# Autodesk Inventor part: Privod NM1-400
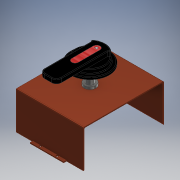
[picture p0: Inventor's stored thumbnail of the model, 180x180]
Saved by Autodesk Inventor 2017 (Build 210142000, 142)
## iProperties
Part Number: Privod NM1-400
Material: Типовые
Document SubType Name: Modeling
Designer: RSagdiev
Density: 1 g/cm^3
Appearance: По умолчанию
Author: RSagdiev
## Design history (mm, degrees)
sketch "Эскиз1"
  geometry: L1 (-37.5, 96.25)-(37.5, 96.25); L2 (37.5, 96.25)-(37.5, 87.75); L3 (37.5, 87.75)-(20.75, 87.75); L4 (-37.5, 87.75)-(-37.5, 96.25); L5 (0, 0)-(119.698, 0); L6 (0, 0)-(-104.809, 0); L7 (0, 94.88)-(0, -60.954); L8 (-20.75, 87.75)-(-16.75, 87.75); L9 (-16.75, 87.75)-(-16.75, 92.75); L10 (-18.75, 94.75)-(-18.75, 94.75); L11 (-20.75, 92.75)-(-20.75, 87.75); L12 (16.75, 87.75)-(16.75, 92.75); L13 (18.75, 94.75)-(18.75, 94.75); L14 (20.75, 87.75)-(16.75, 87.75); L15 (20.75, 92.75)-(20.75, 87.75); L16 (-20.75, 87.75)-(-37.5, 87.75); L17 (-16.75, 87.75)-(-20.75, 87.75); L18 (16.75, 87.75)-(-16.75, 87.75); L19 (20.75, 87.75)-(16.75, 87.75); A1 r 2 centre (-18.75, 92.75) between (-18.75, 94.75) and (-20.75, 92.75); A2 r 2 centre (-18.75, 92.75) between (-16.75, 92.75) and (-18.75, 94.75); A3 r 2 centre (18.75, 92.75) between (18.75, 94.75) and (16.75, 92.75); A4 r 2 centre (18.75, 92.75) between (20.75, 92.75) and (18.75, 94.75); 5 further points
  constraints: 38 end point, 10 point on line, 10 symmetric about line, 8 parallel, 8 point on circle, 4 centre point, 4 horizontal, 4 tangent, 2 perpendicular, 1 concentric, 1 midpoint, 1 vertical, 2 other
  dimensions: "d0" = 87.75 distance between parallel lines of L3 L6 (= 0.5 x Высота); "d1" = 8.5 distance of L1.end L2.end; "d2" = 75 distance between parallel lines of L2 L4 (= 0.5 x Ширина); "d3" = 4 distance of point (-20.75, 94.75) point (-16.75, 94.75); "d4" = 7 distance of point (-16.75, 94.75) L8.end; "d5" = 2 radius of A1 (derived); "d6" = 18.75 distance from line of L4 A1.centre (= 0.25 x d2)
extrude "Выдавливание1" new body sketch "Эскиз1" distance "d7" = 2; taper "d8" = 0 deg
mirror "Зеркальное отражение1"
sketch "Эскиз2"
  geometry: L1 (-37.5, 96.25)-(-37.5, 87.75) reference; L2 (37.5, 87.75)-(37.5, 96.25) reference; L3 (-37.5, -96.25)-(-37.5, -87.75) reference; L4 (37.5, -87.75)-(37.5, -96.25) reference; L5 (-75, 89.75)-(75, 89.75); L6 (75, 89.75)-(75, 87.75); L7 (75, 87.75)-(-75, 87.75); L8 (-75, 87.75)-(-75, 89.75); L9 (-37.5, 87.75)-(-20.75, 87.75) reference
  constraints: 8 end point, 2 parallel, 1 collinear, 1 horizontal, 1 perpendicular
  dimensions: "d13" = 150 distance of L5.start L5.end (= Ширина); "d14" = 2 distance of L5.end L6.end; "d15" = 37.5 distance between parallel lines of L1 L8 (= 0.25 x d13)
extrude "Выдавливание2" join sketch "Эскиз2" distance "d11" = 84 (computed from H1); taper "d12" = 0 deg
mirror "Зеркальное отражение2"
sketch "Эскиз3"
  geometry: L1 (-75, 89.75)-(-37.5, 89.75) reference; L2 (75, -89.75)-(-75, -89.75) reference; L3 (-75, 89.75)-(75, 89.75); L4 (75, 89.75)-(75, -89.75); L5 (75, -89.75)-(-75, -89.75); L6 (-75, -89.75)-(-75, 89.75); 1 further point
  constraints: 8 end point, 2 parallel, 1 horizontal, 1 perpendicular
extrude "Выдавливание3" join sketch "Эскиз3" distance "d16" = 2; taper "d17" = 0 deg
fillet "Сопряжение1" dims "d18" = 2
sketch "Эскиз4"
  geometry: L1 (75, -85.75)-(-75, -85.75) reference; L2 (75, -85.75)-(75, 85.75) reference; L3 (-75, 85.75)-(75, 85.75) reference; L4 (-75, 85.75)-(-75, -85.75) reference; L5 (-75, 85.75)-(-75, -85.75) reference; L6 (-75, -85.75)-(75, 85.75); L7 (75, -85.75)-(75, 85.75) reference; L8 (-75, 85.75)-(75, -85.75); C1 r 5 at (0, 0); 1 further point
  constraints: 4 end point, 1 centre point, 1 coincident
  dimensions: "d19" = 10 diameter of C1
extrude "Выдавливание4" cut sketch "Эскиз4" distance "d20" = 10; taper "d21" = 0 deg
sketch "Эскиз5"
  geometry: C1 r 5 at (0, 0) reference; C2 r 5 at (0, 0); C3 r 8 at (0, 0); 1 further point
  constraints: 2 centre point, 2 coincident
  dimensions: "d22" = 16 diameter of C3
extrude "Выдавливание5" new body sketch "Эскиз5" distance "d23" = 29.33333 (= 0.333333 x H1); taper "d24" = 0 deg
sketch "Эскиз6"
  geometry: C1 r 5 at (0, 0) reference; C2 r 5 at (0, 0); 1 further point
  constraints: 1 centre point, 1 coincident
extrude "Выдавливание6" new body sketch "Эскиз6" distance "d25" = 79.33333 (computed from H1); taper "d26" = 0 deg
sketch "Эскиз7"
  geometry: C1 r 5 at (0, 0) reference; C2 r 13 at (0, 0); C3 r 8 at (0, 0); C4 r 5 at (0, 0); 1 further point
  constraints: 3 centre point, 3 coincident
  dimensions: "d27" = 26 diameter of C2; "d28" = 16 diameter of C3; "d29" = 10 diameter of C4
extrude "Выдавливание7" new body sketch "Эскиз7" distance "d30" = 5; taper "d31" = 0 deg
extrude "Выдавливание8" join sketch "Эскиз7" distance "d32" = 20; taper "d33" = 0 deg
sketch "Эскиз8"
  geometry: C1 r 7 at (0, 0); 1 further point
  constraints: 1 centre point, 1 coincident
  dimensions: "d34" = 14 diameter of C1
extrude "Выдавливание9" new body sketch "Эскиз8" distance "d35" = 3; taper "d36" = 0 deg
fillet "Сопряжение2" dims "d37" = 3
sketch "Эскиз9"
  geometry: L1 (1, 13.17)-(-1, 13.17); L2 (-1, 13.17)-(-1, -13.17); L3 (-1, -13.17)-(1, -13.17); L4 (1, -13.17)-(1, 13.17); L5 (1, 13.17)-(-1, -13.17); L6 (-1, 13.17)-(1, -13.17); L7 (17.109, -1)-(-17.109, -1); L8 (-17.109, -1)-(-17.109, 1); L9 (-17.109, 1)-(17.109, 1); L10 (17.109, 1)-(17.109, -1); L11 (17.109, -1)-(-17.109, 1); L12 (-17.109, -1)-(17.109, 1); C1 r 4 at (0, 0) reference; C2 r 5 at (0, 0) reference; 1 further point
  constraints: 24 end point, 4 midpoint, 4 parallel, 2 horizontal, 2 perpendicular
  dimensions: "d38" = 2 distance of L3.end L2.end; "d39" = 2 distance of L7.end L8.end
extrude "Выдавливание10" cut sketch "Эскиз9" distance "d40" = 1; taper "d41" = 0 deg
sketch "Эскиз10"
  geometry: C1 r 17.5 at (0, 0); A1 r 4 centre (0, 0) between (1, -3.873) and (3.873, -1) reference; 1 further point
  constraints: 1 centre point, 1 coincident
  dimensions: "d42" = 35 diameter of C1
extrude "Выдавливание11" new body sketch "Эскиз10" distance "d43" = 6; taper "d44" = 0 deg; dims "d48" = 3, "d49" = 0
sketch "Эскиз11"
  geometry: C1 r 7 at (0, 0); C2 r 22.5 at (0, 0); 1 further point
  constraints: 2 centre point, 1 coincident
  dimensions: "d45" = 45 diameter of C2
extrude "Выдавливание12" join sketch "Эскиз11" distance "d46" = 6; taper "d47" = 0 deg
sketch "Эскиз12"
  geometry: L1 (-4, -49.361)-(4, -49.361); L2 (10, -43.361)-(10, 10.738); L3 (-10, 10.738)-(-10, -43.361); L4 (-10, -49.361)-(10, 14.361); L5 (10, -49.361)-(-10, 14.361); L6 (-12, 12.738)-(12, 12.738); A1 r 17.5 centre (0, 0) between (10, 14.361) and (0, -17.5) reference; A2 r 17.5 centre (0, 0) between (10, 14.361) and (0, -17.5) reference; A3 r 6 centre (-4, -43.361) between (-10, -43.361) and (-4, -49.361); A4 r 6 centre (4, -43.361) between (4, -49.361) and (10, -43.361); A5 r 2 centre (-12, 10.738) between (-10, 10.738) and (-12, 12.738); A6 r 2 centre (12, 10.738) between (12, 12.738) and (10, 10.738); A7 r 17.5 centre (0, 0) between (12, 12.738) and (-12, 12.738)
  constraints: 16 point on circle, 12 end point, 8 tangent, 6 point on line, 5 centre point, 2 equal radius, 2 horizontal, 2 midpoint, 1 coincident, 1 parallel, 1 perpendicular
  dimensions: "d63" = 20 distance of L4.end L5.end; "d64" = 6 radius of A3; "d66" = 10 distance from line of A1.centre L3; "d67" = 2 radius of A5; "d68" = 2 radius of A6 (derived)
extrude "Выдавливание13" join sketch "Эскиз12" distance "d55" = 10; taper "d56" = 0 deg
fillet "Сопряжение9" dims "d69" = 1
fillet "Сопряжение10" dims "d70" = 1
sketch "Эскиз13"
  geometry: L1 (0, 7.748)-(0, -17.5); L2 (-4, 7.748)-(-4, -17.5); L3 (4, -17.5)-(4, 7.748); A1 r 17.5 centre (0, 0) between (17.5, 0) and (0, -17.5) reference; A2 r 4 centre (0, 7.748) between (4, 7.748) and (-4, 7.748); A3 r 4 centre (0, -17.5) between (-4, -17.5) and (4, -17.5); 2 further points
  constraints: 8 end point, 5 point on circle, 4 tangent, 2 centre point, 1 midpoint, 1 parallel, 1 vertical
  dimensions: "d71" = 8 diameter of A3
extrude "Выдавливание14" cut sketch "Эскиз13" distance "d72" = 0.1; taper "d73" = 0 deg
sketch "Эскиз14"
  geometry: L1 (0, 9.652)-(1.649, 6.796); L2 (1.649, 6.796)-(-1.649, 6.796); L3 (-1.649, 6.796)-(0, 9.652); A1 r 4 centre (0, 7.748) between (4, 7.748) and (-4, 7.748) reference; 2 further points
  constraints: 6 end point, 1 coincident, 7 other
extrude "Выдавливание15" join sketch "Эскиз14" distance "d74" = 0.1; taper "d75" = 0 deg
node "Непосредственное редактирование1"
node "Твердое тело1"
node "Спроецированная петля1"
node "Твердое тело2"
node "Твердое тело3"
node "Твердое тело4"
node "Твердое тело5"
node "Спроецированная петля2"
node "Твердое тело6"
node "Спроецированная петля3"
feature "Масштаб1"
other parameters: "H1" = 88 [user parameter; used in 3 equation terms], "Высота" = 175.5 [user parameter; used in 1 equation term], "Ширина" = 150 [user parameter; used in 2 equation terms], "d76" = 19, "d77" = 19
